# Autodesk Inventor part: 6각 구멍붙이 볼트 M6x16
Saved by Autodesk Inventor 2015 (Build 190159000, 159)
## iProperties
Created: 2026-07
Part Number: 6각 구멍붙이 볼트 M6x16
Material: 일반
Document SubType Name: Modeling
Designer: user
Density: 1 g/cm^3
Appearance: 기본값
Author: user
Author: jhkim
Creation Date: 2026-07-01
Sending System: Autodesk Inventor 2027
Preprocessor: ST-DEVELOPER v20.1
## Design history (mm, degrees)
node "6각 구멍붙이 볼트 M6x161"
body "Solid1"
node "기준1"
